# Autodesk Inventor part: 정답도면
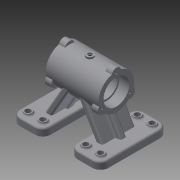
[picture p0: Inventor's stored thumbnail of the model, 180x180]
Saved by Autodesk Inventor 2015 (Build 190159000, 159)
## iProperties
Created: 2026-04
Part Number: 정답도면
Material: 일반
Document SubType Name: Modeling
Designer: User
Density: 1 g/cm^3
Appearance: 기본값
Author: User
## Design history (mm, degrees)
sketch "스케치1"
  geometry: L1 (-72, 55)-(72, 55); L2 (72, 55)-(72, -55); L3 (72, -55)-(-72, -55); L4 (-72, -55)-(-72, 55); L5 (-72, 55)-(72, -55); L6 (72, 55)-(-72, -55); 2 further points
  constraints: 12 end point, 2 midpoint, 2 parallel, 1 coincident, 1 horizontal, 1 perpendicular
  dimensions: "d0" = 144 distance of L2.end L3.end; "d1" = 110 distance of L1.end L2.end
extrude "돌출1" new body sketch "스케치1" distance "d2" = 12; taper "d3" = 0 deg
sketch "스케치2"
  geometry: L1 (144, 0)-(0, 0) reference; L2 (0, -12)-(50, -12); L3 (144, -12)-(0, -12) reference; L4 (50, -12)-(50, 0); L5 (0, -12)-(0, 0); L6 (0, 0)-(50, 0); L7 (0, 0)-(144, 0) reference; L8 (50, -12)-(94, -12); L9 (94, -12)-(94, 0); L10 (94, 0)-(50, 0); L11 (50, 0)-(50, -12); 1 further point
  constraints: 16 end point, 3 perpendicular, 2 parallel, 2 point on line, 1 collinear, 1 horizontal
  dimensions: "d4" = 50 distance of L2.start L2.end; "d5" = 12 distance of L8.end L9.end; "d6" = 44 distance of L2.end L8.end
extrude "돌출2" cut sketch "스케치2" stored distance "d7" = 12; taper "d8" = 0 deg
sketch "스케치4"
  geometry: L1 (55, -12)-(-55, -12) reference; C1 r 29 at (0, 60); 1 further point
  constraints: 1 centre point, 1 vertical alignment
  dimensions: "d14" = 72 distance from line of C1.centre L1; "d134" = 58 diameter of C1
extrude "돌출3" join sketch "스케치4" stored distance "d15" = 86; taper "d16" = 0 deg
sketch "스케치6"
  geometry: L1 (43, 31)-(43, 89) reference; L2 (43, 60)-(-56.517, 60); L3 (-43, 89)-(-43, 31) reference; L4 (-27, 81)-(-43, 81); L5 (43, 81)-(27, 81); L6 (27, 81)-(27, 78); L7 (27, 78)-(-27, 78); L8 (-27, 81)-(-27, 78); L9 (43, 89)-(43, 94); L10 (43, 94)-(33, 94); L11 (43, 89)-(-43, 89) reference; L12 (33, 94)-(28, 89); L13 (-43, 89)-(-43, 94); L14 (-43, 94)-(-33, 94); L15 (-33, 94)-(-28, 89); L16 (43, 81)-(43, 60); L17 (-43, 81)-(-43, 60); L18 (43, 31)-(-43, 31) reference; L19 (-22, -12)-(-72, -12) reference; L20 (43, 60)-(-43, 60); 1 further point
  constraints: 30 end point, 5 perpendicular, 4 point on line, 3 vertical, 2 collinear, 2 equal length, 2 horizontal, 2 midpoint
  dimensions: "d19" = 16 distance of L5.start L5.end; "d20" = 42 diameter of L5 L2; "d21" = 16 distance of L4.start L4.end; "d22" = 36 diameter of L7 L2; "d23" = 42 diameter of L4 L2; "d24" = 10 distance of L9.end L10.end; "d25" = 10 distance of L13.end L14.end; "d26" = 90 deg angle of L12 L15; "d28" = 106 distance between parallel lines of L14 L19
revolve "회전1" sketch "스케치6" stored, may be unused: angle "d29" = 90 deg
sketch "스케치7"
  geometry: L1 (43, 31)-(-43, 31) reference; L2 (17.105, 31)-(32.072, 5.077); L3 (-14.102, 31)-(-32, 0); L4 (0, 31)-(0, 0); L5 (-22, 0)-(-22, -12) reference; L6 (-72, 0)-(-22, 0) reference; L7 (-23.34, 31)-(-41.238, 0); L8 (-37.196, 31)-(-55.094, 0)
  constraints: 10 end point, 7 point on line, 2 parallel, 1 midpoint, 1 vertical
  dimensions: "d30" = 60 deg angle of L3 L2; "d31" = 30 deg angle of L2 L4; "d47" = 10 distance from line of L5 L3.end; "d48" = 8 distance between parallel lines of L3 L7; "d49" = 12 distance between parallel lines of L7 L8
feature "리브3" dims "d50" = 12, "d51" = 10, "d52" = 0, "d53" = 0, "d54" = 1, "d55" = 1
feature "리브4" dims "d56" = 80, "d57" = 8, "d58" = 0, "d59" = 0, "d60" = 1, "d61" = 1
sketch "스케치9"
  geometry: L1 (55, 0)-(-55, 0) reference; L2 (27, 46.083)-(27, 0); L3 (-27, 43.549)-(-27, 0); C1 r 29 at (0, 60) reference; C2 r 29 at (0, 60) reference; 1 further point
  constraints: 4 end point, 2 point on line, 1 perpendicular, 1 vertical
  dimensions: "d63" = 27 distance from line of C1.centre L2; "d64" = 27 distance from line of C1.centre L3
node "작업 평면3"
sketch "스케치11"
  geometry: L1 (41.238, 0)-(23.089, 31.434) reference; 1 further point
feature "리브5" sketch "스케치11" dims "d67" = 10, "d68" = 100, "d69" = 0, "d70" = 0, "d71" = 1, "d72" = 1
sketch "스케치14"
  geometry: L1 (0, 91.373)-(-6, 91.373); L2 (-6, 91.373)-(-6, 88.373); L3 (0, 91.373)-(0, 60); C1 r 18 at (0, 60) reference; A1 r 29 centre (0, 60) between (0, 89) and (-6, 88.373); 2 further points
  constraints: 6 end point, 2 point on circle, 1 centre point, 1 coincident, 1 horizontal, 1 perpendicular, 1 point on line, 1 vertical, 2 other
  dimensions: "d83" = 6 distance of L1.start L1.end; "d84" = 3 distance of L1.end L2.end
revolve "회전2" sketch "스케치14" stored, may be unused: angle "d85" = 90 deg
fillet "모깎기1" dims "d86" = 13
sketch "스케치15"
  geometry: C1 r 6 at (59, 42); C2 r 6 at (59, -42); C3 r 6 at (35, -42); C4 r 6 at (35, 42); A1 r 13 centre (59, 42) between (72, 42) and (59, 55) reference; A2 r 13 centre (35, -42) between (22, -42) and (35, -55) reference; A3 r 13 centre (59, -42) between (59, -55) and (72, -42) reference; A4 r 13 centre (35, 42) between (35, 55) and (22, 42) reference; 1 further point
  constraints: 4 centre point, 4 coincident
  dimensions: "d87" = 12 diameter of C1; "d99" = 12 diameter of C2; "d100" = 12 diameter of C3; "d102" = 12 diameter of C4
extrude "돌출5" join sketch "스케치15" distance "d88" = 3; taper "d89" = 0 deg
hole "구멍1" diameter "d92" = 9; stored, may be unused: countersink angle "d96" = 90 deg, drill point angle "d98" = 118 deg; dims "d90" = 10, "d91" = 10, "d93" = 6, "d94" = 4, "d95" = 2, "d97" = 8
fillet "모깎기2" dims "d101" = 13
hole "구멍2" diameter "d105" = 9; stored, may be unused: countersink angle "d109" = 90 deg, drill point angle "d111" = 118 deg; dims "d103" = 10, "d104" = 10, "d106" = 6, "d107" = 4, "d108" = 2, "d110" = 8
hole "구멍3" diameter "d114" = 9; stored, may be unused: countersink angle "d118" = 90 deg, drill point angle "d120" = 118 deg; dims "d112" = 10, "d113" = 10, "d115" = 6, "d116" = 4, "d117" = 2, "d119" = 8
hole "구멍4" diameter "d123" = 9; stored, may be unused: countersink angle "d127" = 90 deg, drill point angle "d129" = 118 deg; dims "d121" = 10, "d122" = 10, "d124" = 6, "d125" = 4, "d126" = 2, "d128" = 8
sketch "스케치17" dims "d137" = 52
  geometry: C1 r 21 at (0, 0) reference; A1 r 29 centre (0, 0) between (-27.942, -7.761) and (-27.942, 7.761) reference; A2 r 8 centre (-26, 0) between (-27.942, 7.761) and (-27.942, -7.761); 2 further points
  constraints: 4 point on circle, 1 centre point, 1 coincident, 1 horizontal alignment, 2 other
extrude "돌출7" join sketch "스케치17" distance "d139" = 10; taper "d140" = 0 deg
fillet "모깎기3" dims "d144" = 3
fillet "모깎기4" dims "d145" = 3
fillet "모깎기5" dims "d146" = 3
sketch "스케치18"
  geometry: 2 further points
  constraints: 1 other
feature "엠보싱1" sketch "스케치18" dims "d4" = 50, "d5" = 12, "d6" = 44, "d147" = 0.5, "d148" = 0
sketch "스케치19"
  geometry: C1 r 21 at (60, 0) reference; C2 r 26 at (60, 0); A1 r 8 centre (86, 0) between (87.942, -7.761) and (87.942, 7.761) reference; 1 further point
  constraints: 1 centre point, 1 coincident
  dimensions: "d158" = 52 diameter of C2
hole "구멍6" sketch "스케치19" at (86, 0) diameter "d159" = 3.242; stored, may be unused: countersink angle "d163" = 90 deg, drill point angle "d165" = 118 deg; dims "d160" = 8, "d161" = 9.4, "d162" = 2, "d164" = 10
hole "구멍7" diameter "d171" = 5.188; stored, may be unused: countersink angle "d175" = 90 deg, drill point angle "d177" = 118 deg; dims "d169" = 10, "d170" = 10, "d172" = 12, "d173" = 7, "d174" = 2, "d176" = 16
node "작업 평면6"
node "솔리드1"
mirror "대칭1"
mirror "대칭2"
mirror "대칭3"
mirror "대칭4"
mirror "대칭5"
pattern_circular "원형 패턴1" dims angle "d142" = 360 deg
mirror "대칭6"
pattern_circular "원형 패턴2" dims angle "d167" = 360 deg
mirror "대칭7"
mirror "대칭8"
other parameters: "d66" = 27, "d132" = 16, "d138" = 16, "d178" = -72
